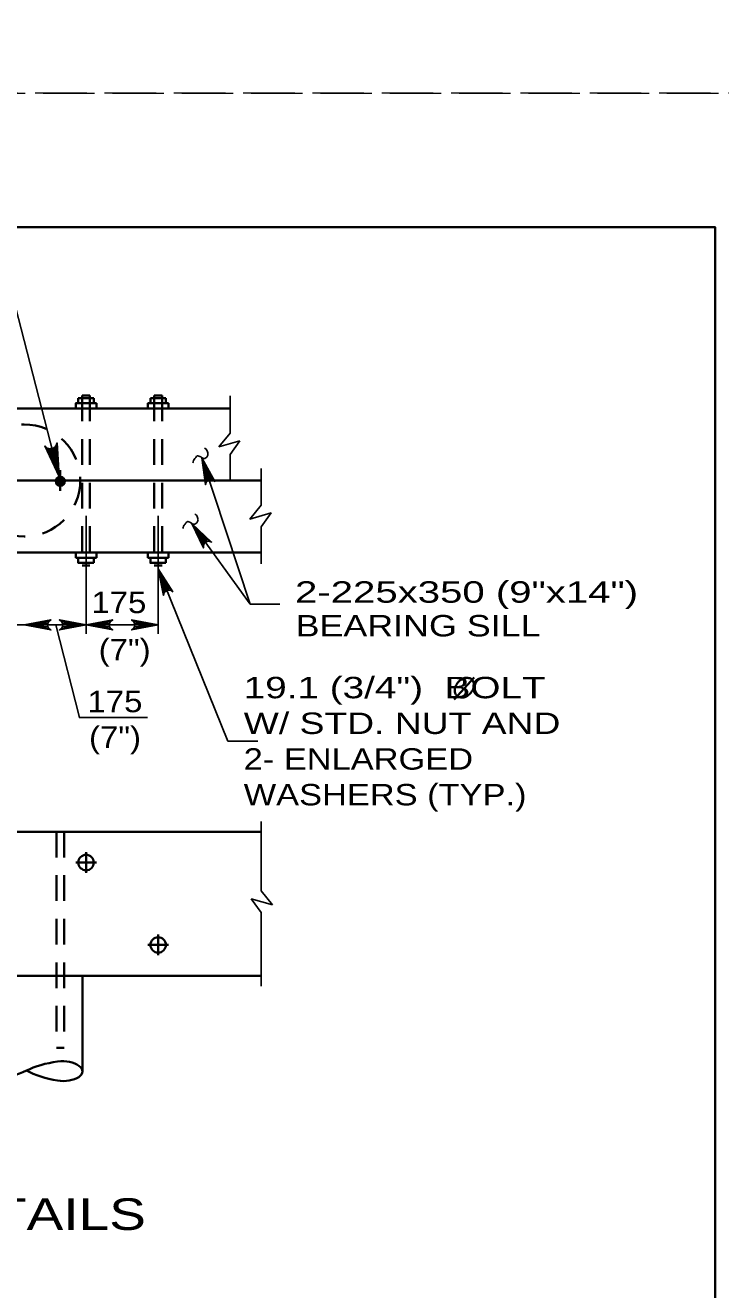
# Model space of a CAD drawing. Extents: x -6.4 to 73.1, y -66 to 0.
# Drawn here: x 29.39 to 33.28, y -50.7 to -43.62 of the extents above; entities that cross this region are included whole.
import ezdxf
from ezdxf.enums import TextEntityAlignment as Align

# ---------------------------------------------------------------- set-up
doc = ezdxf.new("R2010")
doc.units = 0
doc.header["$LTSCALE"] = 0.048
doc.linetypes.add('LONG_DASHED', pattern=[7.5, 6, -1.5])
doc.linetypes.add('MEDIUM_DASHED', pattern=[4.5, 3, -1.5])
for name, color, linetype, lineweight in [('1', 7, 'Continuous', 13), ('4', 7, 'Continuous', 25), ('5', 7, 'Continuous', 25), ('52', 7, 'Continuous', 25), ('63', 7, 'LONG_DASHED', 13)]:
    doc.layers.add(name, color=color, linetype=linetype, lineweight=lineweight)

msp = doc.modelspace()

# ---------------------------------------------------------------- hatches: boundary and pattern name
at = {"layer": '5'}
msp.add_hatch(color=256, dxfattribs=at).paths.add_polyline_path([(30.13167, -46.66392), (30.16683, -46.77708), (30.18508, -46.76967)])

# ---------------------------------------------------------------- linework, layer by layer
at = {"layer": '1', "lineweight": 35}
msp.add_lwpolyline([(1.75, -65.25), (33.25, -65.25), (33.25, -44.75), (1.75, -44.75)], close=True, dxfattribs=at)
at = {"layer": '4', "lineweight": 35}
for p, q in [((29.68475, -45.73642), (29.68475, -45.70758)), ((29.68475, -45.70758), (29.77125, -45.70758)), ((29.70642, -45.69317), (29.74967, -45.69317)), ((29.77125, -45.73642), (29.77125, -45.70758)), ((29.78567, -45.76525), (29.78567, -45.73642)), ((30.08842, -45.73642), (30.08842, -45.70758)), ((30.08842, -45.70758), (30.17492, -45.70758)), ((30.11008, -45.69317), (30.15333, -45.69317)), ((30.17492, -45.73642), (30.17492, -45.70758)), ((30.18933, -45.76525), (30.18933, -45.73642)), ((30.534, -45.76525), (24.30842, -45.76525)), ((30.70842, -46.169), (24.13392, -46.169)), ((29.6415, -46.169), (29.52617, -46.169)), ((29.58383, -46.11133), (29.58383, -46.22667)), ((30.70842, -46.57267), (24.13392, -46.57267)), ((29.67033, -46.57267), (29.67033, -46.6015)), ((29.67033, -46.6015), (29.78567, -46.6015)), ((29.77125, -46.6015), (29.77125, -46.63033)), ((29.78567, -46.57267), (29.78567, -46.6015)), ((30.074, -46.57267), (30.074, -46.6015)), ((30.074, -46.6015), (30.18933, -46.6015)), ((30.17492, -46.6015), (30.17492, -46.63033)), ((30.18933, -46.57267), (30.18933, -46.6015)), ((29.70642, -46.64475), (29.74967, -46.64475)), ((30.11008, -46.64475), (30.15333, -46.64475)), ((30.70842, -48.136), (24.13392, -48.136)), ((29.728, -48.25133), (29.728, -48.36667)), ((29.78567, -48.309), (29.67033, -48.309)), ((30.13167, -48.71275), (30.13167, -48.82808)), ((30.18933, -48.77042), (30.074, -48.77042)), ((30.70842, -48.94342), (24.13392, -48.94342)), ((29.7075, -48.94342), (29.7075, -49.47925)), ((29.56217, -49.34708), (29.60542, -49.34708))]:
    msp.add_line(p, q, dxfattribs=at)
at = {"layer": '4', "linetype": 'MEDIUM_DASHED', "lineweight": 35}
for p, q in [((29.70642, -45.69317), (29.70642, -46.64475)), ((29.74967, -45.69317), (29.74967, -46.64475)), ((30.11008, -45.69317), (30.11008, -46.64475)), ((30.15333, -45.69317), (30.15333, -46.64475)), ((29.56217, -48.136), (29.56217, -49.34708)), ((29.60542, -48.136), (29.60542, -49.34708))]:
    msp.add_line(p, q, dxfattribs=at)
at = {"layer": '4'}
for p, q in [((30.534, -45.90308), (30.534, -45.6945)), ((30.534, -45.90308), (30.47058, -45.981)), ((30.47058, -45.981), (30.58983, -45.94725)), ((30.58983, -45.94725), (30.534, -46.02383)), ((30.534, -46.169), (30.534, -46.02383)), ((30.70842, -46.30675), (30.70842, -46.10167)), ((30.70842, -46.63592), (30.70842, -46.4275)), ((30.70842, -48.07833), (30.70842, -48.46725)), ((30.6525, -48.51142), (30.70842, -48.588)), ((30.77175, -48.54525), (30.6525, -48.51142)), ((30.70842, -48.46725), (30.77175, -48.54525)), ((30.70842, -48.588), (30.70842, -49.00108))]:
    msp.add_line(p, q, dxfattribs=at)
at = {"layer": '4', "lineweight": 35}
for points in [[(29.67033, -45.76525), (29.67033, -45.73642), (29.78567, -45.73642)], [(30.074, -45.76525), (30.074, -45.73642), (30.18933, -45.73642)], [(29.68475, -46.6015), (29.68475, -46.63033), (29.77125, -46.63033)], [(30.08842, -46.6015), (30.08842, -46.63033), (30.17492, -46.63033)]]:
    msp.add_lwpolyline(points, dxfattribs=at)
at = {"layer": '4'}
msp.add_lwpolyline([(30.70842, -46.30675), (30.645, -46.38467), (30.76425, -46.35092), (30.70842, -46.4275)], dxfattribs=at)
at = {"layer": '4', "linetype": 'MEDIUM_DASHED', "lineweight": 35}
msp.add_circle((29.38199, -46.16896), 0.31393, dxfattribs=at)
at = {"layer": '4', "lineweight": 35}
for centre in [(29.72801, -48.30896), (30.13171, -48.77033)]:
    msp.add_circle(centre, 0.04325, dxfattribs=at)
for centre, major_axis, start_param, end_param in [((29.70491, -49.63601), (0.44359, -0.00737), 1.8903203, 2.3561945), ((29.5964, -49.47733), (0.11112, -0.00185), 4.4555879, 8.1107827), ((29.08279, -49.31192), (-0.44359, 0.00737), 1.8903203, 2.3561945), ((29.71012, -49.32234), (0.44359, -0.00737), 3.9269908, 4.392865)]:
    msp.add_ellipse(centre, major_axis=major_axis, ratio=0.5, start_param=start_param, end_param=end_param, dxfattribs=at)
at = {"layer": '5'}
for p, q in [((30.376, -46.04133), (30.647, -46.86125)), ((29.728, -46.366), (29.728, -47.02758)), ((30.13167, -46.366), (30.13167, -47.02758)), ((30.13167, -46.66392), (30.522, -47.62858)), ((27.42117, -46.978), (30.13167, -46.978)), ((30.522, -47.62858), (30.68875, -47.62858))]:
    msp.add_line(p, q, dxfattribs=at)
at = {"layer": '5', "lineweight": 35}
msp.add_line((31.78858, -47.395), (31.90058, -47.27242), dxfattribs=at)
at = {"layer": '5'}
for points in [[(29.57825, -46.14733), (29.33225, -45.1955), (28.82108, -45.1955)], [(29.57825, -46.14733), (29.49775, -45.97558), (29.50442, -45.98133), (29.511, -45.987), (29.518, -45.98908), (29.52492, -45.99108), (29.53125, -45.9905), (29.53758, -45.99), (29.54342, -45.98742), (29.54917, -45.98483), (29.55425, -45.97967), (29.55942, -45.9745), (29.56242, -45.96633), (29.56542, -45.95808), (29.57825, -46.14733), (29.56242, -45.96633), (29.55942, -45.9745), (29.57825, -46.14733), (29.55425, -45.97967), (29.54917, -45.98483), (29.57825, -46.14733), (29.54342, -45.98742), (29.53758, -45.99), (29.57825, -46.14733), (29.53125, -45.9905), (29.52492, -45.99108), (29.57825, -46.14733), (29.518, -45.98908), (29.511, -45.987), (29.57825, -46.14733), (29.50442, -45.98133)], [(30.376, -46.04133), (30.44933, -46.17417), (30.43817, -46.16575), (30.42683, -46.16325), (30.41683, -46.16475), (30.40783, -46.1695), (30.40017, -46.17833), (30.39625, -46.19167), (30.376, -46.04133), (30.40017, -46.17833), (30.40783, -46.1695), (30.376, -46.04133), (30.41683, -46.16475), (30.42683, -46.16325), (30.376, -46.04133), (30.43817, -46.16575)], [(30.32042, -46.40958), (30.647, -46.86125), (30.81375, -46.86125)], [(30.32042, -46.40958), (30.43042, -46.51408), (30.41725, -46.50942), (30.40567, -46.5105), (30.39658, -46.51492), (30.3895, -46.52217), (30.38483, -46.53283), (30.38517, -46.54683), (30.32042, -46.40958), (30.38483, -46.53283), (30.3895, -46.52217), (30.32042, -46.40958), (30.39658, -46.51492), (30.40567, -46.5105), (30.32042, -46.40958), (30.41725, -46.50942)], [(30.13167, -46.66392), (30.2135, -46.79167), (30.20183, -46.784), (30.19033, -46.78225), (30.18042, -46.78442), (30.17183, -46.78975), (30.16475, -46.799), (30.16167, -46.81267), (30.13167, -46.66392), (30.16475, -46.799), (30.17183, -46.78975), (30.13167, -46.66392), (30.18042, -46.78442), (30.19033, -46.78225), (30.13167, -46.66392), (30.20183, -46.784)], [(29.382, -46.978), (29.53117, -47.006), (29.51967, -46.998), (29.51375, -46.988), (29.512, -46.978), (29.51375, -46.968), (29.51967, -46.958), (29.53117, -46.95), (29.382, -46.978), (29.51967, -46.958), (29.51375, -46.968), (29.382, -46.978), (29.512, -46.978), (29.51375, -46.988), (29.382, -46.978), (29.51967, -46.998)], [(29.728, -46.978), (29.57883, -47.006), (29.59033, -46.998), (29.59625, -46.988), (29.598, -46.978), (29.59625, -46.968), (29.59033, -46.958), (29.57883, -46.95), (29.728, -46.978), (29.59033, -46.958), (29.59625, -46.968), (29.728, -46.978), (29.598, -46.978), (29.59625, -46.988), (29.728, -46.978), (29.59033, -46.998)], [(29.728, -46.978), (29.87717, -47.006), (29.86567, -46.998), (29.85975, -46.988), (29.858, -46.978), (29.85975, -46.968), (29.86567, -46.958), (29.87717, -46.95), (29.728, -46.978), (29.86567, -46.958), (29.85975, -46.968), (29.728, -46.978), (29.858, -46.978), (29.85975, -46.988), (29.728, -46.978), (29.86567, -46.998)], [(30.13167, -46.978), (29.9825, -47.006), (29.994, -46.998), (29.99992, -46.988), (30.00167, -46.978), (29.99992, -46.968), (29.994, -46.958), (29.9825, -46.95), (30.13167, -46.978), (29.994, -46.958), (29.99992, -46.968), (30.13167, -46.978), (30.00167, -46.978), (29.99992, -46.988), (30.13167, -46.978), (29.994, -46.998)]]:
    msp.add_lwpolyline(points, dxfattribs=at)
msp.add_lwpolyline([(30.13167, -46.66392), (30.16683, -46.77708), (30.18508, -46.76967)], close=True, dxfattribs=at)
for radius in [0.02667, 0.02, 0.01333, 0.00667]:
    msp.add_circle((29.58383, -46.17343), radius, dxfattribs=at)
for centre, radius, start, end in [((30.46739, -46.13991), 0.1608, 138.37148, 144.4201), ((30.35169, -46.03709), 0.00602, 106.72409, 138.37148), ((30.35204, -46.03824), 0.00722, 77.46905, 106.72408), ((30.33692, -46.10626), 0.0769, 68.59546, 77.46905), ((30.35435, -46.06181), 0.02915, 48.06467, 68.59546), ((30.37187, -46.02318), 0.04045, 39.8006, 60.65202), ((30.38216, -46.0146), 0.02706, 14.23512, 39.8006), ((30.37873, -46.01658), 0.03266, 318.99925, 333.43899), ((30.3875, -46.02096), 0.02285, 333.43899, 350.72014), ((30.33836, -46.02572), 0.07225, 5.70959, 14.23512), ((30.3869, -46.02086), 0.02346, 350.72014, 5.70959), ((30.41115, -46.0978), 0.09068, 153.43899, 161.96079), ((30.40247, -46.09346), 0.08098, 144.4201, 153.43899), ((30.3887, -46.02357), 0.02225, 228.06467, 251.60538), ((30.3875, -46.02718), 0.01844, 251.60538, 287.10557), ((30.38624, -46.02311), 0.0227, 287.10557, 318.99925), ((30.31628, -46.39144), 0.04045, 39.8006, 60.65202), ((30.32657, -46.38286), 0.02706, 14.23512, 39.8006), ((30.28277, -46.39397), 0.07225, 5.70959, 14.23512), ((30.33131, -46.38912), 0.02346, 350.72014, 5.70959), ((30.35556, -46.46606), 0.09068, 153.43899, 161.96079), ((30.34688, -46.46172), 0.08098, 144.4201, 153.43899), ((30.4118, -46.50817), 0.1608, 138.37148, 144.4201), ((30.29611, -46.40535), 0.00602, 106.72409, 138.37148), ((30.29645, -46.40649), 0.00722, 77.46905, 106.72408), ((30.28133, -46.47452), 0.0769, 68.59546, 77.46905), ((30.29876, -46.43006), 0.02915, 48.06467, 68.59546), ((30.33311, -46.39182), 0.02225, 228.06467, 251.60538), ((30.33191, -46.39544), 0.01844, 251.60538, 287.10557), ((30.33066, -46.39136), 0.0227, 287.10557, 318.99925), ((30.32315, -46.38484), 0.03266, 318.99925, 333.43899), ((30.33191, -46.38922), 0.02285, 333.43899, 350.72014)]:
    msp.add_arc(centre, radius, start, end, dxfattribs=at)
at = {"layer": '5', "lineweight": 35}
msp.add_spline([(31.88892, -47.2845), (31.88017, -47.27767), (31.87142, -47.27525), (31.86042, -47.27425), (31.85417, -47.27425), (31.84342, -47.27675), (31.83358, -47.28125), (31.82667, -47.28517), (31.81342, -47.29575), (31.80308, -47.30925), (31.79683, -47.32192), (31.79317, -47.3335), (31.79208, -47.34425), (31.79317, -47.3535), (31.79767, -47.36667), (31.80242, -47.3735), (31.81208, -47.38075), (31.82658, -47.38425), (31.84308, -47.38375), (31.86392, -47.37425), (31.87917, -47.36117), (31.89067, -47.34525), (31.89817, -47.32867), (31.90067, -47.31025), (31.89742, -47.29842), (31.88942, -47.2845)], degree=3, dxfattribs=at)
at = {"layer": '52'}
msp.add_lwpolyline([(29.55875, -46.97792), (29.69125, -47.49683), (30.07283, -47.49683)], dxfattribs=at)
at = {"layer": '63'}
for points in [[(0, -44), (34, -44), (34, -22), (0, -22)], [(0, -66), (34, -66), (34, -44), (0, -44)]]:
    msp.add_lwpolyline(points, close=True, dxfattribs=at)

# ---------------------------------------------------------------- texts
at = {"layer": '5'}
for s, width, p in [('2-225x350 (9"x14")', 1.4, (30.898, -46.85342)), ('BEARING SILL', 1.25, (30.901, -47.04217)), ('19.1 (3/4")  BOLT', 1.35, (30.61042, -47.38867)), ('W/ STD. NUT AND', 1.3, (30.61042, -47.58867)), ('2- ENLARGED', 1.2, (30.61042, -47.78867)), ('WASHERS (TYP.)', 1.2, (30.61042, -47.98867))]:
    msp.add_text(s, height=0.12, dxfattribs=dict(at, width=width)).set_placement(p)
for s, height, width, p in [('175', 0.12, 1.15, (29.91158, -46.91183)), ('(7")', 0.12, 1.15, (29.94408, -47.17583)), ('175', 0.12, 1.15, (29.88967, -47.46683)), ('(7")', 0.12, 1.15, (29.89017, -47.66683)), ('BEARING SILL SPLICE DETAILS', 0.1772, 1.3, (27.73471, -50.36692))]:
    msp.add_text(s, height=height, dxfattribs=dict(at, width=width)).set_placement(p, align=Align.CENTER)

doc.saveas('drawing.dxf')
